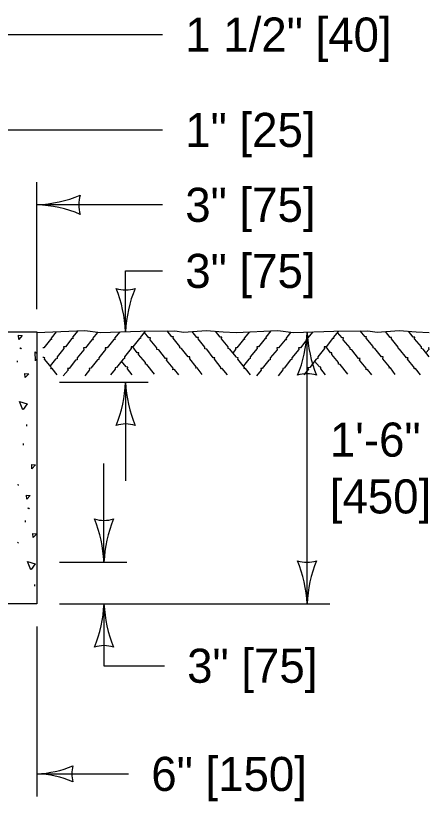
# Model space of a CAD drawing. Extents: x 49991.4 to 50021, y 49987.6 to 50011.4.
# Drawn here: x 50005.147 to 50005.875, y 49992.619 to 49994.003 of the extents above; entities that cross this region are included whole.
import ezdxf

# ---------------------------------------------------------------- set-up
doc = ezdxf.new("R2010")
doc.units = 0
for name, color, linetype in [('Level 1', 7, 'Continuous'), ('Level 2', 7, 'Continuous'), ('Level 3', 7, 'Continuous')]:
    doc.layers.add(name, color=color, linetype=linetype)

msp = doc.modelspace()

# ---------------------------------------------------------------- linework, layer by layer
at = {"layer": 'Level 1'}
for p, q in [((50005.025, 49993.4464), (50005.1847, 49993.4464)), ((50005.1847, 49993.4464), (50005.1847, 49992.967)), ((50005.1544, 49993.4179), (50005.1562, 49993.417)), ((50005.1556, 49993.4179), (50005.1574, 49993.417)), ((50005.1506, 49993.3927), (50005.1504, 49993.3953)), ((50005.1671, 49993.2803), (50005.1669, 49993.2829)), ((50005.1613, 49993.2469), (50005.1611, 49993.2495)), ((50005.1523, 49993.1755), (50005.1519, 49993.1782)), ((50005.1684, 49993.1362), (50005.1702, 49993.1353)), ((50005.1698, 49993.1362), (50005.1714, 49993.1353)), ((50005.1647, 49993.111), (50005.1645, 49993.1137)), ((50005.1503, 49993.0757), (50005.1521, 49993.0748)), ((50005.1811, 49992.9986), (50005.1809, 49993.0013)), ((50005.1847, 49992.967), (50005.025, 49992.967)), ((50005.1751, 49992.967), (50005.175, 49992.9678))]:
    msp.add_line(p, q, dxfattribs=at)
for points in [[(50005.1847, 49993.4449), (50005.2687, 49993.4484), (50005.2964, 49993.445), (50005.3671, 49993.4474), (50005.4272, 49993.4479), (50005.4433, 49993.4458), (50005.4825, 49993.4484), (50005.5123, 49993.4464), (50005.5353, 49993.4453)], [(50005.2569, 49993.4479), (50005.2473, 49993.4367), (50005.2484, 49993.4343), (50005.2462, 49993.4343), (50005.2347, 49993.4196), (50005.2317, 49993.4196), (50005.2323, 49993.417), (50005.2201, 49993.402), (50005.2201, 49993.3991), (50005.2174, 49993.3983), (50005.2081, 49993.3863)], [(50005.3751, 49993.4474), (50005.3663, 49993.436), (50005.3671, 49993.4342), (50005.3649, 49993.4342), (50005.3532, 49993.4195), (50005.3505, 49993.4195), (50005.3507, 49993.4166), (50005.3389, 49993.402), (50005.3389, 49993.399), (50005.3365, 49993.3978), (50005.3249, 49993.3833), (50005.3221, 49993.383), (50005.3224, 49993.3805), (50005.3144, 49993.3705)], [(50005.4755, 49993.3711), (50005.4669, 49993.3827), (50005.4642, 49993.3821), (50005.4648, 49993.3843), (50005.4535, 49993.3987), (50005.4538, 49993.402), (50005.4508, 49993.402), (50005.4393, 49993.417), (50005.4363, 49993.418), (50005.4362, 49993.4203), (50005.4243, 49993.4349), (50005.4251, 49993.4376), (50005.4219, 49993.4376), (50005.4139, 49993.4479)], [(50005.5199, 49993.3702), (50005.5109, 49993.3814), (50005.5085, 49993.3808), (50005.5087, 49993.383), (50005.497, 49993.3978), (50005.4977, 49993.4006), (50005.4949, 49993.4006), (50005.4834, 49993.4159), (50005.4801, 49993.4164), (50005.4801, 49993.4194), (50005.4684, 49993.4336), (50005.469, 49993.436), (50005.4662, 49993.4365), (50005.458, 49993.4466)], [(50005.5353, 49993.402), (50005.5242, 49993.4159), (50005.5212, 49993.4166), (50005.521, 49993.4195), (50005.5093, 49993.4336), (50005.5098, 49993.4367), (50005.507, 49993.4367), (50005.4987, 49993.4474)], [(50005.5353, 49993.4453), (50005.6083, 49993.4484), (50005.6361, 49993.445), (50005.7072, 49993.4474), (50005.7669, 49993.4479), (50005.7836, 49993.4458), (50005.8223, 49993.4484), (50005.852, 49993.4464), (50005.875, 49993.4453)], [(50005.5962, 49993.4479), (50005.5873, 49993.4367), (50005.5883, 49993.4343), (50005.5863, 49993.4343), (50005.5748, 49993.4196), (50005.5715, 49993.4196), (50005.5719, 49993.417), (50005.5601, 49993.402), (50005.5601, 49993.3991), (50005.5573, 49993.3983), (50005.5483, 49993.3863)], [(50005.7151, 49993.4474), (50005.7061, 49993.436), (50005.7072, 49993.4342), (50005.7046, 49993.4342), (50005.6935, 49993.4195), (50005.6903, 49993.4195), (50005.6906, 49993.4166), (50005.6788, 49993.402), (50005.6788, 49993.399), (50005.676, 49993.3978), (50005.6647, 49993.3833), (50005.6616, 49993.383), (50005.6627, 49993.3805), (50005.6541, 49993.3705)], [(50005.815, 49993.3711), (50005.8065, 49993.3827), (50005.8047, 49993.3821), (50005.805, 49993.3843), (50005.7931, 49993.3987), (50005.7938, 49993.402), (50005.7908, 49993.402), (50005.7793, 49993.417), (50005.7764, 49993.418), (50005.7762, 49993.4203), (50005.7642, 49993.4349), (50005.7647, 49993.4376), (50005.7621, 49993.4376), (50005.7537, 49993.4479)], [(50005.8593, 49993.3702), (50005.8505, 49993.3814), (50005.8485, 49993.3808), (50005.8488, 49993.383), (50005.8369, 49993.3978), (50005.8381, 49993.4006), (50005.835, 49993.4006), (50005.8228, 49993.4159), (50005.8206, 49993.4164), (50005.8202, 49993.4194), (50005.8084, 49993.4336), (50005.8085, 49993.436), (50005.8061, 49993.4365), (50005.7981, 49993.4466)], [(50005.875, 49993.402), (50005.8641, 49993.4159), (50005.8614, 49993.4166), (50005.8611, 49993.4195), (50005.8492, 49993.4336), (50005.8496, 49993.4367), (50005.8468, 49993.4367), (50005.8386, 49993.4474)], [(50005.1528, 49993.4329), (50005.1523, 49993.4405), (50005.1589, 49993.4396), (50005.1528, 49993.4329)], [(50005.2186, 49993.4461), (50005.2095, 49993.4351), (50005.2106, 49993.4327), (50005.2084, 49993.4327), (50005.1968, 49993.418), (50005.1953, 49993.418)], [(50005.291, 49993.4449), (50005.2823, 49993.4346), (50005.2836, 49993.4323), (50005.2814, 49993.4323), (50005.27, 49993.418), (50005.2669, 49993.418), (50005.2673, 49993.4146), (50005.2556, 49993.4003), (50005.2556, 49993.3971), (50005.2525, 49993.3964), (50005.2413, 49993.3814), (50005.2383, 49993.3814), (50005.2394, 49993.3786), (50005.2306, 49993.3687)], [(50005.3303, 49993.4461), (50005.3209, 49993.4351), (50005.3221, 49993.4327), (50005.3198, 49993.4327), (50005.3085, 49993.418), (50005.3049, 49993.418), (50005.3056, 49993.4152), (50005.2939, 49993.4004), (50005.2939, 49993.3975), (50005.291, 49993.3966), (50005.2798, 49993.382), (50005.2768, 49993.3817), (50005.2773, 49993.379), (50005.2692, 49993.3688)], [(50005.4341, 49993.3705), (50005.4266, 49993.3801), (50005.424, 49993.3794), (50005.4243, 49993.382), (50005.4129, 49993.3965), (50005.4136, 49993.3991), (50005.4108, 49993.3993), (50005.3989, 49993.4145), (50005.3959, 49993.4149), (50005.3959, 49993.418), (50005.3841, 49993.4322), (50005.3846, 49993.4354), (50005.3817, 49993.4354), (50005.3738, 49993.4453)], [(50005.5589, 49993.4461), (50005.5495, 49993.4351), (50005.5501, 49993.4327), (50005.5483, 49993.4327), (50005.5366, 49993.418), (50005.5353, 49993.418)], [(50005.6311, 49993.4449), (50005.6224, 49993.4346), (50005.6236, 49993.4323), (50005.6214, 49993.4323), (50005.6099, 49993.418), (50005.6066, 49993.418), (50005.6072, 49993.4146), (50005.5953, 49993.4003), (50005.5953, 49993.3971), (50005.5925, 49993.3964), (50005.5812, 49993.3814), (50005.5785, 49993.3814), (50005.5792, 49993.3786), (50005.5709, 49993.3687)], [(50005.6701, 49993.4461), (50005.661, 49993.4351), (50005.6616, 49993.4327), (50005.6597, 49993.4327), (50005.6484, 49993.418), (50005.6452, 49993.418), (50005.6455, 49993.4152), (50005.6334, 49993.4004), (50005.6334, 49993.3975), (50005.6311, 49993.3966), (50005.6199, 49993.382), (50005.6171, 49993.3817), (50005.6176, 49993.379), (50005.6094, 49993.3688)], [(50005.7738, 49993.3705), (50005.7663, 49993.3801), (50005.7641, 49993.3794), (50005.7642, 49993.382), (50005.7525, 49993.3965), (50005.7534, 49993.3991), (50005.7505, 49993.3993), (50005.7387, 49993.4145), (50005.7358, 49993.4149), (50005.7357, 49993.418), (50005.7237, 49993.4322), (50005.7242, 49993.4354), (50005.7215, 49993.4354), (50005.7137, 49993.4453)], [(50005.3916, 49993.3717), (50005.3783, 49993.3886), (50005.3756, 49993.3893), (50005.3755, 49993.392), (50005.3635, 49993.4063), (50005.3638, 49993.4093), (50005.3608, 49993.4093), (50005.3532, 49993.4195)], [(50005.7315, 49993.3717), (50005.7183, 49993.3886), (50005.7154, 49993.3893), (50005.7151, 49993.392), (50005.7035, 49993.4063), (50005.7038, 49993.4093), (50005.7014, 49993.4093), (50005.6934, 49993.4195)], [(50005.1822, 49993.3954), (50005.1817, 49993.4109), (50005.1847, 49993.4087)], [(50005.5353, 49993.418), (50005.5339, 49993.418), (50005.534, 49993.4152), (50005.5298, 49993.4096)], [(50005.875, 49993.418), (50005.8737, 49993.418), (50005.874, 49993.4152), (50005.8695, 49993.4096)], [(50005.1847, 49993.3972), (50005.1824, 49993.3955)], [(50005.2205, 49993.3705), (50005.2118, 49993.3817), (50005.2093, 49993.381), (50005.2101, 49993.3831), (50005.1979, 49993.3978), (50005.1989, 49993.4006), (50005.1962, 49993.4009), (50005.1953, 49993.402)], [(50005.3525, 49993.3707), (50005.3438, 49993.3812), (50005.3444, 49993.3842), (50005.3416, 49993.3843), (50005.3334, 49993.3947)], [(50005.5604, 49993.3705), (50005.5519, 49993.3817), (50005.5495, 49993.381), (50005.5497, 49993.3831), (50005.5379, 49993.3978), (50005.5387, 49993.4006), (50005.5359, 49993.4009), (50005.5353, 49993.402)], [(50005.6923, 49993.3707), (50005.684, 49993.3812), (50005.6843, 49993.3842), (50005.6816, 49993.3843), (50005.6732, 49993.3947)], [(50005.1641, 49993.3655), (50005.1636, 49993.3729), (50005.1702, 49993.3721), (50005.1641, 49993.3655)], [(50005.1601, 49993.309), (50005.1543, 49993.3234), (50005.1676, 49993.3196), (50005.1602, 49993.3092)], [(50005.176, 49993.2052), (50005.1756, 49993.2126), (50005.1822, 49993.212), (50005.176, 49993.2052)], [(50005.1669, 49993.1514), (50005.1662, 49993.1588), (50005.1729, 49993.1579), (50005.1669, 49993.1514)], [(50005.1782, 49993.0838), (50005.1776, 49993.0912), (50005.1844, 49993.0904), (50005.1782, 49993.0838)], [(50005.1742, 49993.0273), (50005.1683, 49993.0417), (50005.1816, 49993.0379), (50005.1744, 49993.0275)]]:
    msp.add_lwpolyline(points, dxfattribs=at)
at = {"layer": 'Level 3'}
for p, q in [((50004.8459, 49993.9697), (50005.4057, 49993.9697)), ((50005.025, 49993.8018), (50005.4057, 49993.8018)), ((50005.1848, 49993.4864), (50005.1848, 49993.7099)), ((50005.4057, 49993.6699), (50005.1848, 49993.6699)), ((50005.3407, 49993.4465), (50005.3407, 49993.5535)), ((50005.3407, 49993.5535), (50005.4057, 49993.5535)), ((50005.66, 49992.967), (50005.66, 49993.4458)), ((50005.2247, 49993.3573), (50005.3807, 49993.3573)), ((50005.3407, 49993.3573), (50005.3407, 49993.1839)), ((50005.3027, 49993.0407), (50005.3027, 49993.2141)), ((50005.2247, 49993.0407), (50005.3427, 49993.0407)), ((50005.2247, 49992.967), (50005.7, 49992.967)), ((50005.3027, 49992.967), (50005.3027, 49992.8582)), ((50005.1847, 49992.927), (50005.1847, 49992.6278)), ((50005.3027, 49992.8582), (50005.409, 49992.8582)), ((50005.1847, 49992.6678), (50005.3459, 49992.6678))]:
    msp.add_line(p, q, dxfattribs=at)
for centre, radius, start, end in [((50005.1733, 49993.9026), 0.233, 272.8273, 292.0772), ((50005.313, 49993.6699), 0.0548, 162.1388, 197.8612), ((50005.1756, 49993.4478), 0.2223, 67.456, 87.6395), ((50005.3407, 49993.5747), 0.0548, 252.1388, 287.8612), ((50005.108, 49993.435), 0.233, 2.8273, 22.0772), ((50005.5628, 49993.4373), 0.2223, 157.456, 177.6395), ((50005.4379, 49993.455), 0.2223, 337.456, 357.6395), ((50005.8927, 49993.4573), 0.233, 182.8273, 202.0772), ((50005.66, 49993.3176), 0.0548, 72.1388, 107.8612), ((50005.1186, 49993.3665), 0.2223, 337.456, 357.6395), ((50005.5734, 49993.3688), 0.233, 182.8273, 202.0772), ((50005.3407, 49993.2291), 0.0548, 72.1388, 107.8612), ((50005.3027, 49993.1689), 0.0548, 252.1388, 287.8612), ((50005.07, 49993.0292), 0.233, 2.8273, 22.0772), ((50005.5248, 49993.0315), 0.2223, 157.456, 177.6395), ((50005.66, 49993.0952), 0.0548, 252.1388, 287.8612), ((50005.4273, 49992.9555), 0.233, 2.8273, 22.0772), ((50005.8821, 49992.9578), 0.2223, 157.456, 177.6395), ((50005.0806, 49992.9762), 0.2223, 337.456, 357.6395), ((50005.5354, 49992.9785), 0.233, 182.8273, 202.0772), ((50005.3027, 49992.8388), 0.0548, 72.1388, 107.8612), ((50005.1751, 49992.8617), 0.1942, 272.8273, 292.0772), ((50005.2915, 49992.6678), 0.0456, 162.1388, 197.8612), ((50005.1771, 49992.4827), 0.1853, 67.456, 87.6395)]:
    msp.add_arc(centre, radius, start, end, dxfattribs=at)

# ---------------------------------------------------------------- texts
at = {"layer": 'Level 2'}
for s, p in [('1 1/2" [40]', (50005.4457, 49993.9397)), ('1" [25]', (50005.4457, 49993.7718)), ('3" [75]', (50005.4457, 49993.6399)), ('3" [75]', (50005.4457, 49993.5235)), ('1\'-6"', (50005.7, 49993.2264)), ('[450]', (50005.7, 49993.1264)), ('3" [75]', (50005.449, 49992.8282))]:
    msp.add_text(s, height=0.06, dxfattribs=at).set_placement(p)
msp.add_text('6" [150]', height=0.06, rotation=359.9543, dxfattribs=at).set_placement((50005.3859, 49992.6378))

doc.saveas('drawing.dxf')
